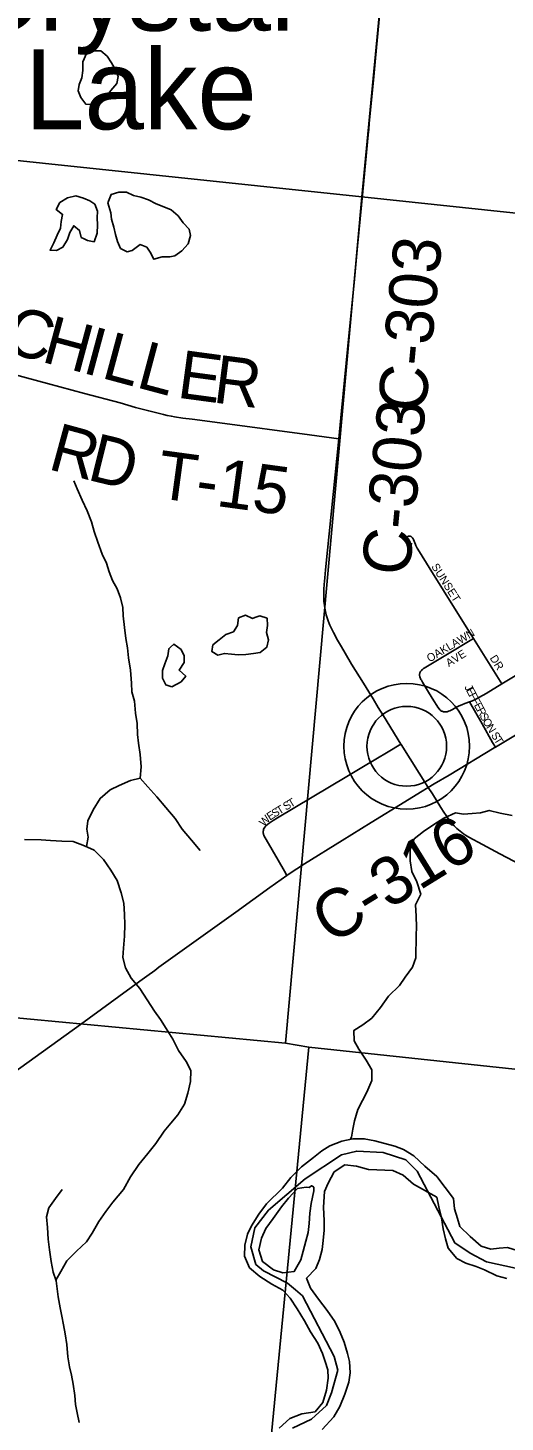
# Model space of a CAD drawing. Extents: x 1410790 to 1770854, y 566777 to 831614.
# Drawn here: x 1542325 to 1545307, y 685042 to 693752 of the extents above; entities that cross this region are included whole.
import ezdxf

# ---------------------------------------------------------------- set-up
doc = ezdxf.new("R2010")
doc.units = 0
for name, color, linetype in [('GM_X_County_Road', 7, 'Continuous'), ('GM_X_County_Road_Text', 7, 'Continuous'), ('GM_X_Major_River', 7, 'Continuous'), ('GM_X_Minor_Lake', 7, 'Continuous'), ('GM_X_Minor_Lake_Text', 7, 'Continuous'), ('GM_X_Minor_River', 7, 'Continuous'), ('GM_X_Section', 7, 'Continuous'), ('GM_X_Township', 7, 'Continuous'), ('GM_X_Township_Road', 7, 'Continuous'), ('GM_X_Township_Road_Text', 7, 'Continuous'), ('GM_X_Township_Subdivision', 7, 'Continuous'), ('GM_X_Township_Subdivision_Text', 7, 'Continuous'), ('GM_X_Unincorporated', 7, 'Continuous'), ('GM_X_Unincorporated_Location', 7, 'Continuous')]:
    doc.layers.add(name, color=color, linetype=linetype)

msp = doc.modelspace()

# ---------------------------------------------------------------- linework, layer by layer
at = {"layer": 'GM_X_County_Road'}
for points in [[(1544497.6, 693563.4), (1544560.1, 694226.6), (1544624.7, 694929.8), (1544680.1, 695509.7)], [(1544454.7, 693116.8), (1544458.3, 693154.8), (1544486.7, 693448.5), (1544497.6, 693563.4)], [(1544451.4, 693083.1), (1544454.7, 693116.8)], [(1544267.1, 691185.5), (1544284.6, 691359.4), (1544332.6, 691849), (1544363.6, 692159), (1544385, 692387.6), (1544418.5, 692730.2), (1544451.4, 693083.1)], [(1544481.5, 689560.5), (1544454.8, 689604), (1544421.4, 689658.6), (1544347.8, 689777.6), (1544307.1, 689846.5), (1544284.4, 689884.6), (1544259.9, 689926.7), (1544233.6, 689974.3), (1544219.2, 690003.8), (1544211.6, 690020.8), (1544208.1, 690030.1), (1544201.9, 690047), (1544197.4, 690059.5), (1544189.7, 690084.5), (1544184.7, 690106.2), (1544180.5, 690126.6), (1544177.7, 690144.5), (1544175, 690170.8), (1544174.3, 690187.5), (1544173.3, 690204), (1544173.4, 690224.2), (1544173.9, 690246), (1544176.1, 690274.4), (1544179.5, 690317.2), (1544184.5, 690365.6), (1544267.1, 691185.5)], [(1544655.8, 689278.2), (1544547.3, 689453.5), (1544514.6, 689507.2), (1544481.5, 689560.5)], [(1545246.7, 689258.1), (1545503.2, 689413.2)], [(1544827.2, 689007.4), (1544657.9, 689274.8), (1544655.8, 689278.2)], [(1544863.8, 689029), (1544957.4, 689084.6), (1545238.9, 689253.4), (1545246.7, 689258.1)], [(1543943.8, 688457.6), (1543956.8, 688466.8), (1544053, 688529.5), (1544289.7, 688676.4), (1544470.8, 688788.3), (1544679.7, 688917.8), (1544777.8, 688977.2), (1544827.2, 689007.4)], [(1544827.2, 689007.4), (1544863.8, 689029)], [(1544852.5, 688967.1), (1544827.2, 689007.4)], [(1545448.8, 688499.9), (1545273.4, 688592.4), (1545193.3, 688635), (1545138.3, 688664.4), (1545107.8, 688680.8), (1545080.2, 688696.7), (1545060.2, 688708.5), (1545046.1, 688717.8), (1545025.6, 688733.1), (1545005.6, 688750.2), (1544988.5, 688766.6), (1544973.8, 688783.1), (1544955.6, 688806), (1544939.2, 688831.2), (1544923.9, 688853.5), (1544905.7, 688882.3), (1544852.5, 688967.1)], [(1543068.7, 687828.8), (1543117, 687864.3), (1543143, 687884.1), (1543623.5, 688228.6), (1543836.2, 688381.9), (1543943.8, 688457.6)], [(1542042.6, 687084.4), (1542228.1, 687219.7), (1542653.4, 687527.1), (1543024.7, 687796.5), (1543068.7, 687828.8)]]:
    msp.add_lwpolyline(points, dxfattribs=at)
at = {"layer": 'GM_X_Major_River'}
for points in [[(1544985, 686439.7), (1544879.3, 686575.6), (1544804.8, 686641.8), (1544736.4, 686705.8), (1544671.3, 686745.6), (1544617.6, 686765.1), (1544546, 686785.1), (1544492.2, 686798.6), (1544426.4, 686812.4), (1544356.2, 686812.3), (1544285.6, 686798.1), (1544212.6, 686768), (1544161.6, 686737.2), (1544110.3, 686694.5), (1544034.5, 686636.3), (1543968.5, 686569.9), (1543916.6, 686503.1)], [(1544881, 686448.3), (1544733.6, 686529.3), (1544670.9, 686585.2), (1544605.6, 686615), (1544505.4, 686617.7), (1544453.3, 686621.1), (1544377.6, 686641.2), (1544305.6, 686649.1), (1544238.2, 686604.8), (1544200.3, 686535.6), (1544178.8, 686482)], [(1543916.6, 686503.1), (1543815.5, 686405.1), (1543767.8, 686342.1), (1543721.9, 686269.1), (1543696.4, 686215.6), (1543680.7, 686147.8), (1543678.9, 686079.6), (1543709.1, 686006.7), (1543773.9, 685952.9), (1543848.8, 685904.9), (1543918, 685867), (1543962.8, 685815.8), (1544007.2, 685750.5), (1544053.4, 685675.1), (1544091.7, 685605.9), (1544136, 685534.6), (1544166.5, 685471.7), (1544183.2, 685421.2), (1544199.9, 685368.6), (1544200.6, 685316.4), (1544190.7, 685242.5), (1544168.6, 685164.8), (1544119, 685105.9), (1544036.5, 685093.9), (1543961.7, 685065.8), (1543896, 685005.2)], [(1544010.5, 686502.4), (1543952.8, 686441.7), (1543909.3, 686386.7), (1543857.3, 686313.8), (1543811.6, 686250.8), (1543784, 686191.3), (1543768.1, 686117.5), (1543790.3, 686044.7), (1543859.1, 685992.9), (1543918.8, 685975.3), (1543989.2, 685983.6), (1544031.1, 686056.7), (1544044.5, 686110.5), (1544062.1, 686172.2), (1544075.5, 686226), (1544083, 686282), (1544086.7, 686348.1), (1544094.2, 686408), (1544110.7, 686487.9)], [(1544110.7, 686487.9), (1544111.3, 686509.9), (1544103.5, 686516.1), (1544097.5, 686518.3), (1544083.2, 686508.7), (1544063.1, 686510.2), (1544010.5, 686502.4)], [(1544178.8, 686482), (1544171.8, 686386), (1544175.6, 686299.7), (1544176.2, 686241.5), (1544170.5, 686177.5), (1544163.1, 686121.5), (1544147.4, 686057.8), (1544123.9, 686002.2), (1544066.2, 685941.5), (1544090.7, 685878.7), (1544141.1, 685811.3), (1544195.4, 685739.7), (1544243.7, 685670.3), (1544276, 685601.3), (1544300.6, 685542.5), (1544322.8, 685471.8), (1544333.5, 685421.4), (1544337.8, 685351.1), (1544330.2, 685291.1), (1544306.3, 685217.5), (1544274.2, 685140.1), (1544236.5, 685074.9), (1544164.3, 684996.5)], [(1545316.9, 685940), (1545255.2, 685955.6), (1545178, 685993.6), (1545126.4, 686015), (1545060.8, 686034.7), (1545005.4, 686064.2), (1544951, 686129.7), (1544934.4, 686186.3), (1544920, 686248.8), (1544909.7, 686319.3), (1544893.5, 686387.9), (1544881, 686448.3)], [(1545749, 686474), (1545746.9, 686370.3), (1545735.5, 686316.5), (1545719.8, 686250.7), (1545706.1, 686186.9), (1545686.4, 686121.2), (1545636.8, 686064.3), (1545568.4, 686054), (1545510.6, 686067.5), (1545453, 686085), (1545381.6, 686114.8), (1545321.9, 686132.4), (1545269.7, 686129.7), (1545217.4, 686123), (1545157.7, 686140.5), (1545089.2, 686202.4), (1545024.6, 686264.2), (1545009.8, 686314.7), (1544991.4, 686375.4), (1544985, 686439.7)]]:
    msp.add_lwpolyline(points, dxfattribs=at)
at = {"layer": 'GM_X_Minor_Lake'}
for points in [[(1542889, 693447.9), (1542873.4, 693486.2), (1542848, 693532.6), (1542820.5, 693575), (1542780.8, 693607.6), (1542736.8, 693608.1), (1542690.5, 693590.7), (1542667.9, 693538.9), (1542667.5, 693507.2)], [(1542667.5, 693507.2), (1542667.2, 693484.8), (1542662.6, 693440.7), (1542646.1, 693398.9), (1542639.6, 693358.9), (1542655.1, 693316.6), (1542686.6, 693276.1), (1542728.6, 693273.6), (1542770.7, 693277), (1542811.3, 693318.6), (1542843.8, 693360.3), (1542880.4, 693403.9), (1542889, 693447.9)], [(1542742.9, 692650.1), (1542711.1, 692670.6), (1542671.3, 692687.1), (1542623.4, 692701.8), (1542573.2, 692690.3), (1542524.8, 692660.9), (1542502.2, 692617.1), (1542541.9, 692586.5), (1542533.3, 692542.5), (1542528.8, 692500.5), (1542508.2, 692456.7), (1542487.6, 692408.9), (1542463, 692363.1), (1542503, 692360.6), (1542543.3, 692382.1), (1542571.9, 692429.8), (1542586.5, 692473.8), (1542611, 692515.5), (1542646.7, 692487), (1542658.2, 692442.8), (1542675.3, 692434.8)], [(1543191.4, 692321.8), (1543211.3, 692321.6), (1543243.4, 692327.2), (1543285.8, 692358.7), (1543326.4, 692402.3), (1543341.1, 692454.2), (1543331.6, 692494.4), (1543296, 692533), (1543264.5, 692577.4), (1543221, 692616.1), (1543175.2, 692634.7), (1543125.3, 692653.3), (1543077.6, 692678), (1543029.7, 692694.6), (1542983.8, 692705.2), (1542940, 692725.8), (1542894, 692726.4), (1542845.7, 692711), (1542825.1, 692659.1)], [(1542675.3, 692434.8), (1542698, 692424.2), (1542737.9, 692415.7), (1542758.6, 692469.6), (1542759.3, 692521.7), (1542757.8, 692565.8), (1542760.4, 692607.8), (1542742.9, 692650.1)], [(1542825.1, 692659.1), (1542842.3, 692596.8), (1542847.8, 692556.6), (1542861.2, 692506.4), (1542872.6, 692460.1), (1542884.1, 692417.9), (1542903.6, 692373.6), (1542945.4, 692353), (1542975.5, 692360.6), (1543026, 692398.1), (1543067.9, 692381.5), (1543089.5, 692351.2), (1543111, 692306.8), (1543163.3, 692322.2), (1543191.4, 692321.8)], [(1543743.2, 690067.7), (1543727.7, 690062.6), (1543683.9, 690083.2), (1543641.7, 690065.7), (1543635.1, 690017.7), (1543608.6, 689979.9), (1543562.3, 689962.4), (1543519.8, 689928.9), (1543481.4, 689897.3), (1543474.9, 689855.3), (1543512.6, 689832.8)], [(1543512.6, 689832.8), (1543552.8, 689844.3), (1543596.8, 689839.8), (1543638.8, 689835.2), (1543686.9, 689836.6), (1543735, 689844), (1543777.1, 689849.5), (1543817.6, 689883.1), (1543828.2, 689929), (1543816.7, 689975.3), (1543821.3, 690019.3), (1543819.8, 690063.4), (1543774, 690078), (1543743.2, 690067.7)], [(1543216.5, 689883.5), (1543204.8, 689872.8), (1543200.2, 689828.7), (1543179.6, 689778.9), (1543165, 689737), (1543166.4, 689688.9), (1543186, 689648.5), (1543223.9, 689636)], [(1543223.9, 689636), (1543282.3, 689667.4), (1543310.8, 689701.1), (1543269.2, 689739.7), (1543301.8, 689787.4), (1543300.3, 689829.5), (1543282.8, 689867.8), (1543237.2, 689902.4), (1543216.5, 689883.5)]]:
    msp.add_lwpolyline(points, dxfattribs=at)
at = {"layer": 'GM_X_Minor_River'}
for points in [[(1542690.6, 688637.6), (1542701.6, 688696.7), (1542692.2, 688746.9), (1542698.8, 688798.9), (1542731.7, 688866.7), (1542776.7, 688938.2), (1542839.4, 688991.6), (1542895.8, 689018.9), (1542966.3, 689050.1), (1543026.5, 689065.4), (1543033.4, 689135.4), (1543026.3, 689211.7), (1543015.2, 689283.9), (1543009.9, 689338.1), (1543006.7, 689406.3), (1542997.5, 689470.5), (1542990.5, 689546.8), (1542975.2, 689605.1), (1542971.9, 689659.2), (1542964.9, 689739.5), (1542953.8, 689815.8), (1542946.6, 689878), (1542937.3, 689938.2), (1542928.1, 690006.5), (1542921, 690078.7), (1542917.7, 690130.9), (1542902.4, 690191.2), (1542883.1, 690247.5), (1542853.7, 690300), (1542832.4, 690354.4), (1542815, 690408.7), (1542789.7, 690463.2), (1542762.6, 690539.6), (1542739.4, 690606.1), (1542722.1, 690666.4), (1542695, 690734.9), (1542663.7, 690801.4), (1542632.6, 690871.9), (1542611.2, 690922.3)], [(1543026.5, 689065.4), (1543073.9, 689010.7), (1543131.2, 688947.8), (1543186.4, 688881), (1543245.6, 688812.1), (1543288.8, 688745.4), (1543348.1, 688678.5), (1543401.3, 688613.8)], [(1544337.8, 686808.6), (1544346, 686822.3), (1544354.7, 686872.3), (1544365.3, 686924.2), (1544386.2, 686996.1), (1544415, 687051.9), (1544443.6, 687103.6), (1544474.6, 687175.4), (1544473.4, 687243.5), (1544438.1, 687304.1), (1544392.9, 687372.8), (1544363.5, 687423.3), (1544362.4, 687489.4), (1544416.9, 687524.8), (1544473.4, 687566.2), (1544528.3, 687631.6), (1544579.3, 687703.2), (1544646.2, 687770.4), (1544682.9, 687822.1), (1544727.7, 687883.7), (1544748.4, 687943.5), (1544750.2, 688083.8), (1544752.8, 688133.8), (1544751.7, 688202), (1544746.6, 688274.2), (1544779.4, 688339.9), (1544754.4, 688416.4), (1544725.1, 688480.9), (1544714, 688549.2), (1544712.8, 688619.3), (1544737.7, 688685.1), (1544796.3, 688732.5), (1544860.9, 688775.8), (1544923.5, 688815.1), (1544996, 688848.2), (1545048, 688839.5), (1545102.1, 688844.9), (1545152.2, 688848.3), (1545208.4, 688863.6), (1545276.3, 688846.7), (1545350.2, 688831.7)], [(1542922.3, 686495.4), (1542965.4, 686575.1), (1543018.4, 686650.6), (1543073.3, 686720), (1543124.2, 686783.5), (1543177.2, 686859), (1543217.9, 686910.6), (1543262.6, 686962.2), (1543303.4, 687027.8), (1543324.3, 687097.7), (1543341.2, 687169.6), (1543342.1, 687237.7), (1543314.8, 687294.2), (1543265.6, 687362.9), (1543230.4, 687433.5), (1543199, 687484), (1543153.9, 687556.7), (1543116.5, 687609.3), (1543069.3, 687680), (1543024.1, 687750.8), (1542970.9, 687815.5), (1542935.6, 687880.1), (1542918.4, 687944.5), (1542921.2, 688002.5), (1542928.1, 688078.6), (1542931, 688150.7), (1542927.8, 688212.9), (1542924.7, 688283.1), (1542907.5, 688349.4), (1542882.4, 688425.9), (1542843.1, 688490.5), (1542797.9, 688557.2), (1542738.6, 688616.1), (1542678.9, 688642.9), (1542607.1, 688669.8), (1542537.1, 688670.7), (1542465, 688675.6), (1542407, 688680.4), (1542302.9, 688681.7)], [(1542644.8, 685039.9), (1542631.7, 685100.2), (1542622.4, 685152.4), (1542617.2, 685208.6), (1542608.2, 685278.8), (1542597, 685335.1), (1542585.7, 685387.4), (1542574.6, 685449.6), (1542567.7, 685527.9), (1542556.6, 685594.1), (1542547.4, 685650.4), (1542536.2, 685704.6), (1542527, 685756.9), (1542513.9, 685825.2), (1542506.6, 685875.4), (1542501.3, 685925.5), (1542482.1, 685979.9), (1542471, 686046.2), (1542460.1, 686118.5), (1542451, 686184.7), (1542448.1, 686258.9), (1542441, 686325.1), (1542455.8, 686381), (1542496.7, 686438.5), (1542538.4, 686495.7)], [(1542500.2, 685928.7), (1542530.2, 685983.2), (1542567.2, 686048.8), (1542628.1, 686110.1), (1542691, 686169.3), (1542725.8, 686222.9), (1542768.9, 686294.5), (1542811.8, 686358), (1542854.7, 686415.5), (1542922.3, 686495.4)]]:
    msp.add_lwpolyline(points, dxfattribs=at)
at = {"layer": 'GM_X_Section'}
for points in [[(1539645, 698570.3), (1544924.5, 698045), (1544412, 692697.3), (1539075.1, 693257.5)], [(1544924.5, 698045), (1550226.2, 697504.9), (1549679, 692139.1), (1544412, 692697.3)], [(1539075.1, 693257.5), (1544412, 692697.3), (1543934.6, 687408.9), (1538798.3, 687891.7), (1538630.6, 687908.5)], [(1544412, 692697.3), (1549679, 692139.1), (1549133, 686845.3), (1544080.1, 687384.4), (1543934.6, 687408.9)], [(1538798.3, 687891.7), (1543934.6, 687408.9), (1544080.1, 687384.4), (1543575.1, 682144.2), (1538284.9, 682626)], [(1544080.1, 687384.4), (1549133, 686845.3), (1549540.4, 686810.9), (1549042.5, 681629.8), (1543575.1, 682144.2)]]:
    msp.add_lwpolyline(points, close=True, dxfattribs=at)
at = {"layer": 'GM_X_Township'}
msp.add_lwpolyline([(1543978.5, 685004.7), (1544096.5, 685059.8), (1544190.9, 685146.4), (1544222.4, 685225.1), (1544261.6, 685366.6), (1544238, 685453.1), (1544041.3, 685830.6), (1543996.6, 685867.9), (1543946.9, 685909.3), (1543797.4, 685987.9), (1543750.2, 686027.2), (1543718.7, 686137.4), (1543742.3, 686255.3), (1543828.9, 686365.5), (1544056.9, 686562.2), (1544285.1, 686711.7), (1544379.5, 686735.3), (1544544.8, 686727.4), (1544686.4, 686680.2), (1544757.2, 686609.5), (1544993.3, 686161.2), (1545087.7, 686098.3), (1545190, 686043.2), (1545371, 686003.9)], dxfattribs=at)
msp.add_lwpolyline([(1543978.5, 685004.7), (1544096.5, 685059.8), (1544190.9, 685146.4), (1544222.4, 685225.1), (1544261.6, 685366.6), (1544238, 685453.1), (1544041.3, 685830.6), (1543996.6, 685867.9), (1543946.9, 685909.3), (1543797.4, 685987.9), (1543750.2, 686027.2), (1543718.7, 686137.4), (1543742.3, 686255.3), (1543828.9, 686365.5), (1544056.9, 686562.2), (1544285.1, 686711.7), (1544379.5, 686735.3), (1544544.8, 686727.4), (1544686.4, 686680.2), (1544757.2, 686609.5), (1544993.3, 686161.2), (1545087.7, 686098.3), (1545190, 686043.2), (1545371, 686003.9)], dxfattribs=at)
at = {"layer": 'GM_X_Township_Road'}
msp.add_lwpolyline([(1541657.1, 691741.2), (1541684.8, 691734.1), (1541796.4, 691705.7), (1542446.3, 691529.8), (1542679.3, 691468.6), (1542901.8, 691408.5), (1542997.9, 691381.3), (1543080.1, 691359.4), (1543171.5, 691336.1), (1543195.9, 691330.6), (1543221.6, 691325.5), (1543241.9, 691322.2), (1543293.8, 691314.5), (1543351.9, 691306.8), (1543525, 691284.7), (1544085.3, 691208.6), (1544267.1, 691185.5)], dxfattribs=at)
at = {"layer": 'GM_X_Township_Subdivision'}
for points in [[(1545110.1, 689938.1), (1545012.4, 690094.4), (1544832.8, 690380.8), (1544772.9, 690477.9), (1544758.1, 690501), (1544752.7, 690510.3), (1544749.1, 690518.9), (1544746.8, 690525), (1544743, 690535), (1544738.9, 690545.6), (1544734.2, 690555.8), (1544732.1, 690559.6), (1544730, 690563), (1544728.2, 690565.4), (1544725.6, 690568.5), (1544723.6, 690570.3), (1544722.1, 690571.6), (1544720.3, 690572.9), (1544719.1, 690573.8), (1544717.7, 690574.6), (1544715.9, 690575.6), (1544714.3, 690576.4), (1544712.1, 690577.2), (1544710.4, 690577.6), (1544709, 690577.7), (1544707.2, 690577.6), (1544705.7, 690577.4), (1544703.8, 690576.8), (1544701.1, 690575.8), (1544698.7, 690574.7), (1544697.2, 690573.7), (1544695.7, 690572.5), (1544694.5, 690571.4), (1544693.3, 690569.9), (1544692.1, 690568.2), (1544691.3, 690566.7), (1544690.9, 690565), (1544690.5, 690563.3), (1544690.3, 690561.3), (1544690.2, 690559.6), (1544690.3, 690557.6), (1544690.6, 690555.4), (1544691.2, 690553.7), (1544691.9, 690552.1), (1544692.8, 690550.4), (1544693.9, 690548.8), (1544695, 690547.4), (1544696.8, 690545.3), (1544698.7, 690543.7), (1544703.5, 690540), (1544707.3, 690537.4), (1544711.4, 690534.9), (1544717.7, 690531.3), (1544722.2, 690528.9), (1544726.7, 690526.7)], [(1544922.6, 689479.6), (1544918.2, 689480.7), (1544913.5, 689482.4), (1544909.8, 689484.2), (1544906.2, 689486.5), (1544902.8, 689489.6), (1544899.9, 689492.5), (1544894.3, 689498.9), (1544887.5, 689507.7), (1544879.4, 689519.1), (1544861.6, 689547.8), (1544828.4, 689601.6), (1544790.5, 689664.9), (1544783.9, 689676.1), (1544781.1, 689680.7), (1544778, 689687.1), (1544776.8, 689689.9), (1544775.9, 689692.2), (1544774.1, 689698.2), (1544773.3, 689702.1), (1544772.9, 689705.1), (1544772.6, 689707.5), (1544772.6, 689709.6), (1544772.6, 689712.8), (1544772.7, 689714.5), (1544773, 689716.6), (1544773.5, 689719), (1544774.3, 689721.5), (1544775, 689723.3), (1544776.5, 689726.7), (1544778.9, 689730.9), (1544780.7, 689733.5), (1544784.1, 689737.8), (1544787.5, 689741.2), (1544790.7, 689744.1), (1544793.6, 689746.5), (1544797.5, 689749.2), (1544802, 689752), (1544810.7, 689757.6), (1544936.1, 689832.4), (1545110.1, 689938.1)], [(1545287.5, 689654.2), (1545110.1, 689938.1)], [(1545287.5, 689654.2), (1545551.9, 689813.1), (1545588.8, 689836.5)], [(1545084.9, 689541.1), (1545102.5, 689548.6), (1545123.1, 689558.6), (1545188.4, 689594.7), (1545287.5, 689654.2)], [(1544922.6, 689479.6), (1544926.5, 689479), (1544930.6, 689478.4), (1544934.3, 689478.2), (1544939.6, 689478.8), (1544945.6, 689480.2), (1544953.4, 689482.8), (1544961.4, 689485.8), (1544969.1, 689488.9), (1545019.7, 689516.3), (1545036.3, 689523.8), (1545054.6, 689530.3), (1545084.9, 689541.1)], [(1545246.7, 689258.1), (1545229, 689288.7), (1545162.7, 689403.6), (1545084.9, 689541.1)], [(1544317.3, 689075.3), (1544422.8, 689138.6), (1544576.4, 689230.4), (1544655.8, 689278.2)], [(1543943.8, 688457.6), (1543928.8, 688483), (1543887.7, 688552.5), (1543812.9, 688681.1), (1543806.9, 688692.3), (1543801.6, 688703.1), (1543799.3, 688708.5), (1543797.4, 688713.6), (1543796.5, 688716.9), (1543795.7, 688720.8), (1543795.3, 688724.8), (1543795.2, 688729.1), (1543795.5, 688733.4), (1543796.1, 688737.4), (1543796.8, 688741.3), (1543797.8, 688744.4), (1543800.1, 688750.3), (1543801.7, 688753.5), (1543804.9, 688758.3), (1543807, 688761.1), (1543809.7, 688764.4), (1543814, 688768.9), (1543816.9, 688771.6), (1543821.6, 688775.6), (1543831.8, 688783.1), (1543844.7, 688792.1), (1543857.1, 688800.6), (1543884.2, 688817.6), (1544102, 688946), (1544317.3, 689075.3)]]:
    msp.add_lwpolyline(points, dxfattribs=at)
at = {"layer": 'GM_X_Unincorporated'}
for radius in [392.8, 249]:
    msp.add_circle((1544692.2, 689264), radius, dxfattribs=at)
at = {"layer": 'GM_X_Unincorporated_Location'}
msp.add_line((1544692.2, 689264), (1544692.2, 689264), dxfattribs=at)

# ---------------------------------------------------------------- texts
at = {"layer": 'GM_X_County_Road_Text'}
for s, rotation, p in [('C-303', 84.48114, (1544809.1, 691343.8)), ('C-303', 84.48171, (1544707.9, 690323)), ('C-316', 31.71795, (1544220.7, 688020))]:
    msp.add_text(s, height=300, rotation=rotation, dxfattribs=at).set_placement(p)
at = {"layer": 'GM_X_Minor_Lake_Text'}
for s, rotation, p in [('Crystal', 0.00846, (1541911.4, 693734)), ('Lake', 0.00854, (1542306, 693118.2))]:
    msp.add_text(s, height=499.98, rotation=rotation, dxfattribs=at).set_placement(p)
at = {"layer": 'GM_X_Township_Road_Text'}
for s, rotation, p in [('C', 344.92799, (1542163.5, 691732.2)), ('H', 344.92603, (1542401.5, 691668.1)), ('I', 344.92804, (1542656.4, 691599.5)), ('L', 344.92855, (1542775.4, 691567.4)), ('L', 345.0834, (1542992.9, 691508.8)), ('E', 352.33623, (1543250.4, 691443)), ('R', 352.68499, (1543474.8, 691412.8)), ('R', 344.77946, (1542442.5, 690997.8)), ('D', 346.1037, (1542687.5, 690931.2)), ('T-15', 352.26562, (1543119.9, 690817.1))]:
    msp.add_text(s, height=300, rotation=rotation, dxfattribs=at).set_placement(p)
at = {"layer": 'GM_X_Township_Subdivision_Text'}
for s, rotation, p in [('SUNSET', 302.47184, (1544843.8, 690387)), ('OAKLAWN', 30.828, (1544835.4, 689787.2)), ('AVE', 32.00415, (1544955.6, 689758.2)), ('DR', 302.00478, (1545209, 689815)), ('J', 297.91433, (1545051, 689634)), ('E', 297.91616, (1545061.3, 689614.5)), ('F', 297.92142, (1545077.7, 689583.4)), ('F', 297.92142, (1545094.2, 689552.3)), ('E', 297.92142, (1545110.7, 689521.2)), ('R', 297.91748, (1545127.2, 689490.1)), ('S', 298.00325, (1545145.8, 689455.1)), ('O', 300.55907, (1545163.5, 689421.9)), ('N', 301.95016, (1545186.5, 689382.8)), ('S', 302.00678, (1545216.8, 689334.3)), ('T', 302.00678, (1545235.5, 689304.4)), ('S', 31.37841, (1543937.6, 688861.3)), ('T', 31.36674, (1543967.7, 688879.6)), ('W', 46.50415, (1543800, 688759.4)), ('E', 32.61786, (1543836.9, 688798.8)), ('S', 31.58692, (1543866.3, 688817.7)), ('T', 31.37841, (1543896.3, 688836.1))]:
    msp.add_text(s, height=50, rotation=rotation, dxfattribs=at).set_placement(p)

doc.saveas('drawing.dxf')
